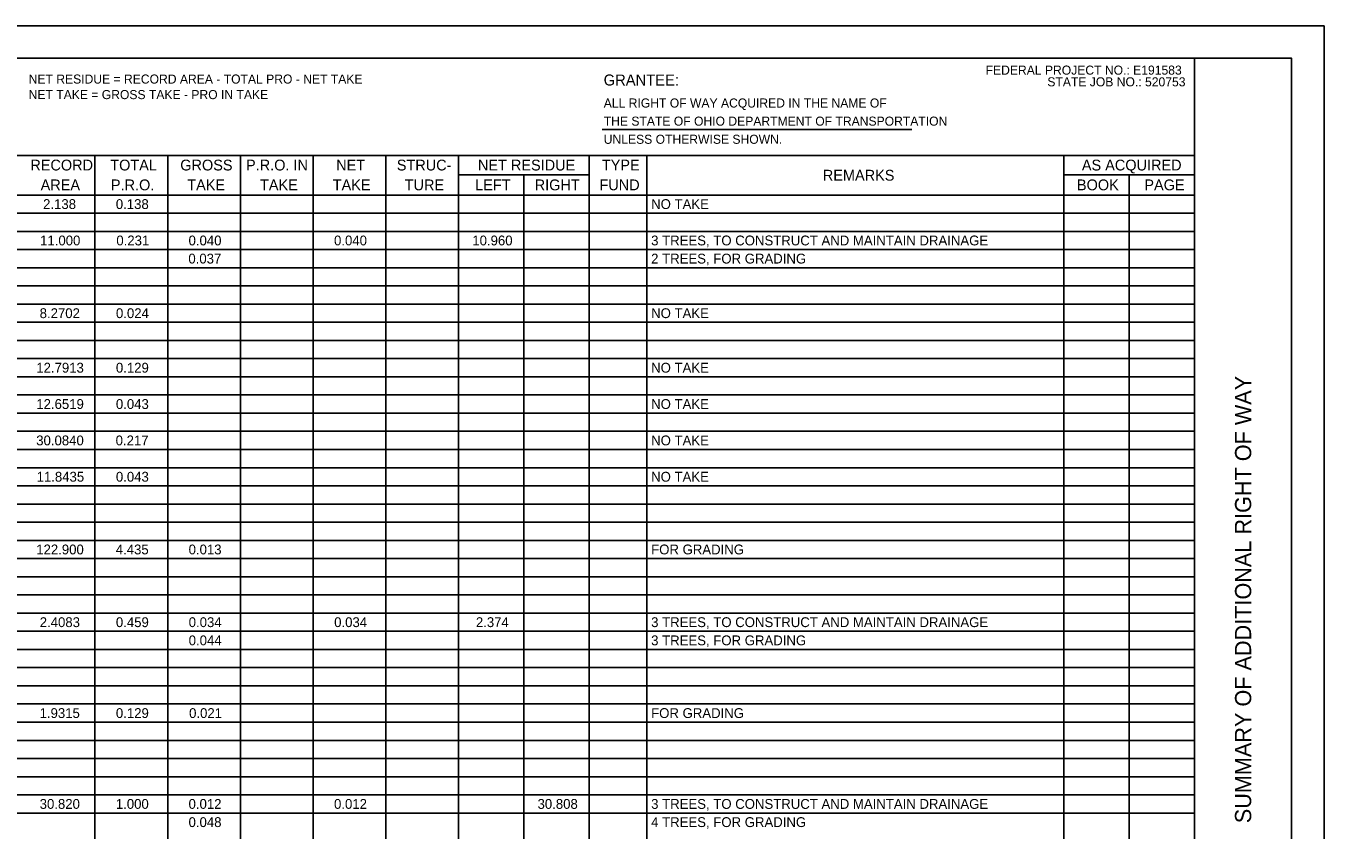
# Model space of a CAD drawing. Extents: x 0 to 34, y 0 to 22.
# Drawn here: x 13.96 to 34, y 9.58 to 22 of the extents above; entities that cross this region are included whole.
import ezdxf

# ---------------------------------------------------------------- set-up
doc = ezdxf.new("R2010")
doc.units = 0
for name, color, linetype in [('SH_Border', 7, 'Continuous'), ('SH_Cut_Line', 7, 'Continuous'), ('SH_Data', 7, 'Continuous'), ('SH_Text', 7, 'Continuous')]:
    doc.layers.add(name, color=color, linetype=linetype)

msp = doc.modelspace()

# ---------------------------------------------------------------- linework, layer by layer
at = {"layer": 'SH_Border'}
msp.add_line((32, 0.5), (32, 21.5), dxfattribs=at)
msp.add_lwpolyline([(1.5, 21.5), (33.5, 21.5), (33.5, 0.5), (1.5, 0.5)], close=True, dxfattribs=at)
at = {"layer": 'SH_Cut_Line'}
msp.add_lwpolyline([(0, 0), (34, 0), (34, 22), (0, 22)], close=True, dxfattribs=at)
at = {"layer": 'SH_Text'}
for p, q in [((22.857, 20.403), (27.637, 20.403)), ((1.5, 20), (32, 20)), ((1.5, 20), (32, 20)), ((15.024, 20), (15.024, 3.107)), ((16.147, 20), (16.147, 3.107)), ((17.27, 20), (17.27, 3.107)), ((18.393, 20), (18.393, 3.107)), ((19.516, 20), (19.516, 3.107)), ((20.639, 20), (20.639, 3.107)), ((22.653, 20), (22.653, 3.107)), ((23.545, 20), (23.545, 3.107)), ((29.985, 20), (29.985, 3.107)), ((32, 20), (32, 3.107)), ((20.639, 19.703), (22.653, 19.703)), ((21.646, 19.703), (21.646, 3.107)), ((29.985, 19.703), (32, 19.703)), ((30.993, 19.703), (30.993, 3.107)), ((1.5, 19.389), (32, 19.389)), ((1.5, 19.108), (32, 19.108)), ((1.5, 18.828), (32, 18.828)), ((1.5, 18.547), (32, 18.547)), ((1.5, 18.266), (32, 18.266)), ((1.5, 17.985), (32, 17.985)), ((1.5, 17.705), (32, 17.705)), ((1.5, 17.424), (32, 17.424)), ((1.5, 17.143), (32, 17.143)), ((1.5, 16.862), (32, 16.862)), ((1.5, 16.582), (32, 16.582)), ((1.5, 16.301), (32, 16.301)), ((1.5, 16.02), (32, 16.02)), ((1.5, 15.74), (32, 15.74)), ((1.5, 15.459), (32, 15.459)), ((1.5, 15.178), (32, 15.178)), ((1.5, 14.897), (32, 14.897)), ((1.5, 14.617), (32, 14.617)), ((1.5, 14.336), (32, 14.336)), ((1.5, 14.055), (32, 14.055)), ((1.5, 13.774), (32, 13.774)), ((1.5, 13.494), (32, 13.494)), ((1.5, 13.213), (32, 13.213)), ((1.5, 12.932), (32, 12.932)), ((1.5, 12.652), (32, 12.652)), ((1.5, 12.371), (32, 12.371)), ((1.5, 12.09), (32, 12.09)), ((1.5, 11.809), (32, 11.809)), ((1.5, 11.529), (32, 11.529)), ((1.5, 11.248), (32, 11.248)), ((1.5, 10.967), (32, 10.967)), ((1.5, 10.687), (32, 10.687)), ((1.5, 10.406), (32, 10.406)), ((1.5, 10.125), (32, 10.125)), ((1.5, 9.844), (32, 9.844))]:
    msp.add_line(p, q, dxfattribs=at)

# ---------------------------------------------------------------- texts
at = {"layer": 'SH_Data'}
msp.add_text('SUMMARY OF ADDITIONAL RIGHT OF WAY', height=0.25, rotation=90, dxfattribs=at).set_placement((32.875, 9.687))
at = {"layer": 'SH_Text'}
for s, height, p in [('NET RESIDUE = RECORD AREA - TOTAL PRO - NET TAKE', 0.14, (14, 21.11)), ('GRANTEE:', 0.17, (22.878, 21.08)), ('FEDERAL PROJECT NO.: E191583', 0.14, (28.775, 21.248)), ('STATE JOB NO.: 520753', 0.14, (29.728, 21.067)), ('NET TAKE = GROSS TAKE - PRO IN TAKE', 0.14, (14, 20.87)), ('ALL RIGHT OF WAY ACQUIRED IN THE NAME OF', 0.14, (22.879, 20.74)), ('THE STATE OF OHIO DEPARTMENT OF TRANSPORTATION', 0.14, (22.879, 20.46)), ('UNLESS OTHERWISE SHOWN.', 0.14, (22.879, 20.18)), ('RECORD', 0.1671, (14.026, 19.768)), ('TOTAL', 0.1671, (15.26, 19.768)), ('GROSS', 0.1671, (16.341, 19.768)), ('P.R.O. IN', 0.1671, (17.356, 19.768)), ('NET', 0.1671, (18.748, 19.768)), ('STRUC-', 0.1671, (19.684, 19.768)), ('NET RESIDUE', 0.16711, (20.937, 19.768)), ('TYPE', 0.1671, (22.85, 19.768)), ('AS ACQUIRED', 0.16711, (30.261, 19.768)), ('REMARKS', 0.1671, (26.262, 19.611)), ('AREA', 0.1671, (14.185, 19.462)), ('P.R.O.', 0.1671, (15.27, 19.462)), ('TAKE', 0.1671, (16.449, 19.462)), ('TAKE', 0.1671, (17.572, 19.462)), ('TAKE', 0.1671, (18.695, 19.462)), ('TURE', 0.1671, (19.806, 19.462)), ('LEFT', 0.1671, (20.895, 19.462)), ('RIGHT', 0.1671, (21.813, 19.462)), ('FUND', 0.1671, (22.813, 19.462)), ('BOOK', 0.1671, (30.185, 19.462)), ('PAGE', 0.1671, (31.226, 19.462)), ('2.138', 0.1519, (14.223, 19.173)), ('0.138', 0.1519, (15.346, 19.173)), ('NO TAKE', 0.1519, (23.611, 19.173)), ('11.000', 0.1519, (14.177, 18.611)), ('0.231', 0.1519, (15.354, 18.611)), ('0.040', 0.1519, (16.469, 18.611)), ('0.040', 0.1519, (18.715, 18.611)), ('10.960', 0.1519, (20.85, 18.611)), ('3 TREES, TO CONSTRUCT AND MAINTAIN DRAINAGE', 0.15192, (23.611, 18.611)), ('0.037', 0.1519, (16.466, 18.331)), ('2 TREES, FOR GRADING', 0.15192, (23.611, 18.331)), ('8.2702', 0.1519, (14.17, 17.488)), ('0.024', 0.1519, (15.348, 17.488)), ('NO TAKE', 0.1519, (23.611, 17.488)), ('12.7913', 0.1519, (14.118, 16.646)), ('0.129', 0.1519, (15.347, 16.646)), ('NO TAKE', 0.1519, (23.611, 16.646)), ('12.6519', 0.1519, (14.118, 16.085)), ('0.043', 0.1519, (15.347, 16.085)), ('NO TAKE', 0.1519, (23.611, 16.085)), ('30.0840', 0.1519, (14.117, 15.523)), ('0.217', 0.1519, (15.343, 15.523)), ('NO TAKE', 0.1519, (23.611, 15.523)), ('11.8435', 0.1519, (14.123, 14.962)), ('0.043', 0.1519, (15.347, 14.962)), ('NO TAKE', 0.1519, (23.611, 14.962)), ('122.900', 0.1519, (14.117, 13.839)), ('4.435', 0.1519, (15.345, 13.839)), ('0.013', 0.1519, (16.47, 13.839)), ('FOR GRADING', 0.15192, (23.611, 13.839)), ('2.4083', 0.1519, (14.171, 12.716)), ('0.459', 0.1519, (15.347, 12.716)), ('0.034', 0.1519, (16.471, 12.716)), ('0.034', 0.1519, (18.717, 12.716)), ('2.374', 0.1519, (20.905, 12.716)), ('3 TREES, TO CONSTRUCT AND MAINTAIN DRAINAGE', 0.15192, (23.611, 12.716)), ('0.044', 0.1519, (16.471, 12.435)), ('3 TREES, FOR GRADING', 0.15192, (23.611, 12.435)), ('1.9315', 0.1519, (14.169, 11.312)), ('0.129', 0.1519, (15.347, 11.312)), ('0.021', 0.1519, (16.477, 11.312)), ('FOR GRADING', 0.15192, (23.611, 11.312)), ('30.820', 0.1519, (14.17, 9.909)), ('1.000', 0.1519, (15.346, 9.909)), ('0.012', 0.1519, (16.469, 9.909)), ('0.012', 0.1519, (18.715, 9.909)), ('30.808', 0.1519, (21.857, 9.909)), ('3 TREES, TO CONSTRUCT AND MAINTAIN DRAINAGE', 0.15192, (23.611, 9.909)), ('0.048', 0.1519, (16.469, 9.628)), ('4 TREES, FOR GRADING', 0.15192, (23.611, 9.628))]:
    msp.add_text(s, height=height, dxfattribs=at).set_placement(p)

doc.saveas('drawing.dxf')
